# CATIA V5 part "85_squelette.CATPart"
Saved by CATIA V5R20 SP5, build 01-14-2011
Part number: 85_squelette
Publications: "Plan yz", "Plan.5", "Plan.7", "Plan.8"
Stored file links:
  C:\Documents and Settings\anizard\Bureau\13\85_squelette.CATPart
  C:\Documents and Settings\anizard\Bureau\13\anizard.CATProduct
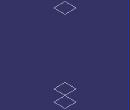
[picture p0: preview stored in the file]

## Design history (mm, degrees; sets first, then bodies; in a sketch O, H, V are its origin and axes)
Parameters
  epaisseur = 8 mm
Set1
  Plane1: linked copy from another document
Body1 (main body)
  Plane2: type Offset, RefPlane Plane1, Offset 2.1, reversed
  Plane3: type Offset, RefPlane Plane2, Offset 1.3, reversed
  Plane4: type Offset, RefPlane Plane3, Offset 8, reversed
